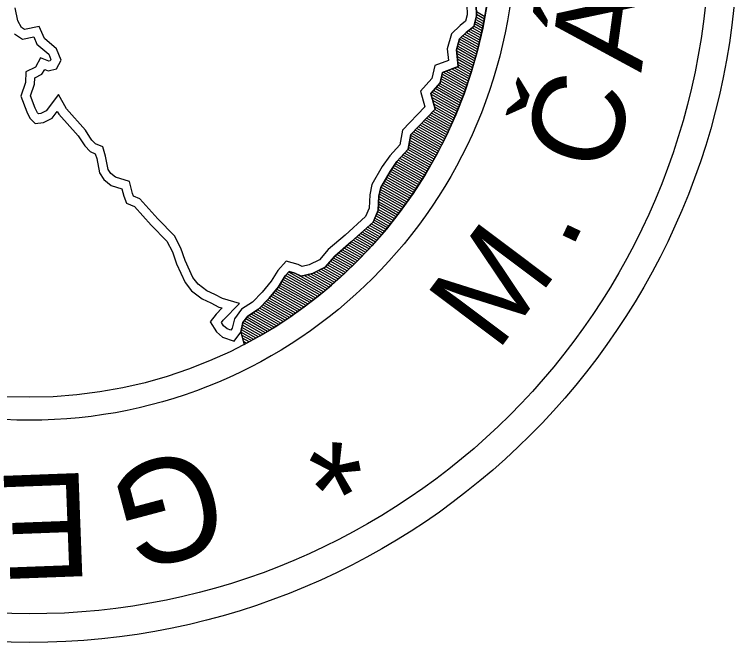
# Model space of a CAD drawing. Extents: x -821057 to -820632, y -1070881 to -1069829.
# Drawn here: x -820964.313 to -820960.375, y -1069882.387 to -1069878.964 of the extents above; entities that cross this region are included whole.
import ezdxf

# ---------------------------------------------------------------- set-up
doc = ezdxf.new("R2010")
doc.units = 0
doc.layers.add('Popisove_pole', color=7, linetype='Continuous')

msp = doc.modelspace()

# ---------------------------------------------------------------- linework, layer by layer
at = {"layer": 'Popisove_pole'}
for p, q in [((-820961.7512, -1069878.9763), (-820961.7975, -1069878.9501)), ((-820961.7536, -1069878.9893), (-820961.7969, -1069878.9648)), ((-820961.7611, -1069879.0281), (-820961.8049, -1069879.0034)), ((-820961.7585, -1069879.0152), (-820961.8016, -1069878.9909)), ((-820961.756, -1069879.0023), (-820961.7984, -1069878.9784)), ((-820961.772, -1069879.0794), (-820961.8318, -1069879.0456)), ((-820961.7692, -1069879.0666), (-820961.8211, -1069879.0373)), ((-820961.7664, -1069879.0538), (-820961.8114, -1069879.0284)), ((-820961.7637, -1069879.041), (-820961.8082, -1069879.0159)), ((-820961.7838, -1069879.1301), (-820961.8722, -1069879.0802)), ((-820961.7808, -1069879.1175), (-820961.8627, -1069879.0712)), ((-820961.7778, -1069879.1048), (-820961.8533, -1069879.0622)), ((-820961.7748, -1069879.0921), (-820961.8426, -1069879.0539)), ((-820961.7967, -1069879.1803), (-820961.8969, -1069879.1237)), ((-820961.7934, -1069879.1678), (-820961.8934, -1069879.1113)), ((-820961.7901, -1069879.1553), (-820961.8898, -1069879.099)), ((-820961.7869, -1069879.1427), (-820961.8816, -1069879.0892)), ((-820961.8069, -1069879.2176), (-820961.9056, -1069879.1618)), ((-820961.8034, -1069879.2052), (-820961.9041, -1069879.1483)), ((-820961.8, -1069879.1928), (-820961.9005, -1069879.136)), ((-820961.8104, -1069879.23), (-820961.9038, -1069879.1772)), ((-820961.814, -1069879.2423), (-820961.902, -1069879.1926)), ((-820961.8177, -1069879.2546), (-820961.9002, -1069879.208)), ((-820961.8214, -1069879.2668), (-820961.8984, -1069879.2234)), ((-820961.8252, -1069879.2791), (-820961.8965, -1069879.2387)), ((-820961.849, -1069879.3518), (-820961.9785, -1069879.2786)), ((-820961.8449, -1069879.3397), (-820961.9633, -1069879.2728)), ((-820961.8408, -1069879.3277), (-820961.9482, -1069879.267)), ((-820961.8368, -1069879.3156), (-820961.933, -1069879.2612)), ((-820961.8329, -1069879.3034), (-820961.9178, -1069879.2555)), ((-820961.829, -1069879.2913), (-820961.9026, -1069879.2497)), ((-820961.8617, -1069879.3877), (-820961.9895, -1069879.3154)), ((-820961.8574, -1069879.3757), (-820961.9865, -1069879.3027)), ((-820961.8532, -1069879.3638), (-820961.9835, -1069879.2901)), ((-820961.8794, -1069879.4351), (-820962.0142, -1069879.3589)), ((-820961.8748, -1069879.4233), (-820962.0059, -1069879.3493)), ((-820961.8704, -1069879.4115), (-820961.9975, -1069879.3396)), ((-820961.866, -1069879.3996), (-820961.9925, -1069879.3281)), ((-820961.8979, -1069879.482), (-820962.0445, -1069879.3992)), ((-820961.8932, -1069879.4704), (-820962.0394, -1069879.3878)), ((-820961.8885, -1069879.4586), (-820962.031, -1069879.3781)), ((-820961.8839, -1069879.4469), (-820962.0226, -1069879.3685)), ((-820961.9027, -1069879.4937), (-820962.0397, -1069879.4163)), ((-820961.9076, -1069879.5053), (-820962.0348, -1069879.4334)), ((-820961.9125, -1069879.5169), (-820962.0299, -1069879.4505)), ((-820961.9174, -1069879.5285), (-820962.0251, -1069879.4676)), ((-820961.9378, -1069879.5744), (-820962.0502, -1069879.5109)), ((-820961.9326, -1069879.563), (-820962.0413, -1069879.5015)), ((-820961.9275, -1069879.5515), (-820962.0324, -1069879.4922)), ((-820961.9224, -1069879.54), (-820962.0235, -1069879.4829)), ((-820961.9644, -1069879.6311), (-820962.0947, -1069879.5575)), ((-820961.959, -1069879.6198), (-820962.0858, -1069879.5482)), ((-820961.9536, -1069879.6085), (-820962.0769, -1069879.5388)), ((-820961.9483, -1069879.5972), (-820962.068, -1069879.5295)), ((-820961.943, -1069879.5858), (-820962.0591, -1069879.5202)), ((-820961.9867, -1069879.6759), (-820962.1303, -1069879.5948)), ((-820961.9811, -1069879.6648), (-820962.1214, -1069879.5855)), ((-820961.9755, -1069879.6536), (-820962.1125, -1069879.5761)), ((-820961.9699, -1069879.6424), (-820962.1036, -1069879.5668)), ((-820962.0099, -1069879.7203), (-820962.1569, -1069879.6372)), ((-820962.004, -1069879.7092), (-820962.1545, -1069879.6242)), ((-820961.9982, -1069879.6982), (-820962.1482, -1069879.6134)), ((-820961.9924, -1069879.6871), (-820962.1393, -1069879.6041)), ((-820962.0278, -1069879.7532), (-820962.1642, -1069879.6762)), ((-820962.0218, -1069879.7423), (-820962.1617, -1069879.6632)), ((-820962.0158, -1069879.7313), (-820962.1593, -1069879.6502)), ((-820962.0463, -1069879.7859), (-820962.1798, -1069879.7104)), ((-820962.0401, -1069879.775), (-820962.1712, -1069879.7009)), ((-820962.0339, -1069879.7641), (-820962.1666, -1069879.6892)), ((-820962.0716, -1069879.829), (-820962.2144, -1069879.7483)), ((-820962.0652, -1069879.8183), (-820962.2058, -1069879.7388)), ((-820962.0588, -1069879.8075), (-820962.1971, -1069879.7293)), ((-820962.0525, -1069879.7967), (-820962.1885, -1069879.7199)), ((-820962.0978, -1069879.8716), (-820962.2457, -1069879.788)), ((-820962.0912, -1069879.861), (-820962.2386, -1069879.7777)), ((-820962.0846, -1069879.8504), (-820962.2314, -1069879.7674)), ((-820962.0781, -1069879.8397), (-820962.223, -1069879.7578)), ((-820962.1249, -1069879.9137), (-820962.2735, -1069879.8298)), ((-820962.118, -1069879.9033), (-820962.2672, -1069879.819)), ((-820962.1112, -1069879.8927), (-820962.26, -1069879.8087)), ((-820962.1045, -1069879.8822), (-820962.2529, -1069879.7983)), ((-820962.1528, -1069879.9554), (-820962.2984, -1069879.8731)), ((-820962.1457, -1069879.945), (-820962.2921, -1069879.8623)), ((-820962.1387, -1069879.9346), (-820962.2859, -1069879.8515)), ((-820962.1318, -1069879.9242), (-820962.2797, -1069879.8406)), ((-820962.1743, -1069879.9863), (-820962.3171, -1069879.9056)), ((-820962.1671, -1069879.976), (-820962.3108, -1069879.8948)), ((-820962.1599, -1069879.9657), (-820962.3046, -1069879.884)), ((-820962.1964, -1069880.0169), (-820962.3257, -1069879.9439)), ((-820962.189, -1069880.0068), (-820962.3231, -1069879.931)), ((-820962.1816, -1069879.9965), (-820962.3205, -1069879.9181)), ((-820962.2189, -1069880.0473), (-820962.3295, -1069879.9848)), ((-820962.2113, -1069880.0372), (-820962.3287, -1069879.9709)), ((-820962.2038, -1069880.0271), (-820962.3279, -1069879.957)), ((-820962.2419, -1069880.0774), (-820962.332, -1069880.0264)), ((-820962.2342, -1069880.0674), (-820962.3312, -1069880.0125)), ((-820962.2265, -1069880.0573), (-820962.3303, -1069879.9986)), ((-820962.2654, -1069880.1071), (-820962.3451, -1069880.0621)), ((-820962.2575, -1069880.0972), (-820962.3403, -1069880.0504)), ((-820962.2497, -1069880.0873), (-820962.3356, -1069880.0387)), ((-820962.2975, -1069880.1464), (-820962.3698, -1069880.1056)), ((-820962.2894, -1069880.1366), (-820962.36, -1069880.0968)), ((-820962.2814, -1069880.1268), (-820962.3545, -1069880.0855)), ((-820962.2733, -1069880.117), (-820962.3498, -1069880.0738)), ((-820962.339, -1069880.1948), (-820962.4188, -1069880.1497)), ((-820962.3306, -1069880.1852), (-820962.409, -1069880.1408)), ((-820962.3222, -1069880.1755), (-820962.3992, -1069880.132)), ((-820962.3139, -1069880.1659), (-820962.3894, -1069880.1232)), ((-820962.3057, -1069880.1561), (-820962.3796, -1069880.1144)), ((-820962.3732, -1069880.2329), (-820962.458, -1069880.1849)), ((-820962.3645, -1069880.2234), (-820962.4482, -1069880.1761)), ((-820962.356, -1069880.2139), (-820962.4384, -1069880.1673)), ((-820962.3474, -1069880.2043), (-820962.4286, -1069880.1585)), ((-820962.4172, -1069880.2798), (-820962.5077, -1069880.2286)), ((-820962.4083, -1069880.2705), (-820962.4977, -1069880.22)), ((-820962.3994, -1069880.2611), (-820962.4876, -1069880.2113)), ((-820962.3906, -1069880.2517), (-820962.4776, -1069880.2026)), ((-820962.3819, -1069880.2423), (-820962.4678, -1069880.1938)), ((-820962.4536, -1069880.3167), (-820962.5479, -1069880.2633)), ((-820962.4444, -1069880.3075), (-820962.5379, -1069880.2547)), ((-820962.4353, -1069880.2983), (-820962.5278, -1069880.246)), ((-820962.4262, -1069880.289), (-820962.5178, -1069880.2373)), ((-820962.4909, -1069880.353), (-820962.5849, -1069880.2999)), ((-820962.4814, -1069880.344), (-820962.5765, -1069880.2903)), ((-820962.4721, -1069880.3349), (-820962.568, -1069880.2807)), ((-820962.4628, -1069880.3258), (-820962.558, -1069880.272)), ((-820962.5388, -1069880.3977), (-820962.6305, -1069880.3459)), ((-820962.5291, -1069880.3888), (-820962.6186, -1069880.3383)), ((-820962.5195, -1069880.3799), (-820962.6102, -1069880.3287)), ((-820962.5099, -1069880.371), (-820962.6018, -1069880.3191)), ((-820962.5003, -1069880.362), (-820962.5933, -1069880.3095)), ((-820962.6396, -1069880.4843), (-820962.8279, -1069880.3779)), ((-820962.6292, -1069880.4758), (-820962.8194, -1069880.3684)), ((-820962.6189, -1069880.4673), (-820962.7694, -1069880.3823)), ((-820962.5985, -1069880.4501), (-820962.7176, -1069880.3828)), ((-820962.5884, -1069880.4415), (-820962.6994, -1069880.3788)), ((-820962.5784, -1069880.4328), (-820962.6836, -1069880.3734)), ((-820962.5684, -1069880.4241), (-820962.6703, -1069880.3665)), ((-820962.5585, -1069880.4153), (-820962.657, -1069880.3596)), ((-820962.5486, -1069880.4065), (-820962.6438, -1069880.3528)), ((-820962.6818, -1069880.5179), (-820962.8565, -1069880.4192)), ((-820962.6711, -1069880.5096), (-820962.8499, -1069880.4086)), ((-820962.6606, -1069880.5012), (-820962.8433, -1069880.398)), ((-820962.6501, -1069880.4928), (-820962.8364, -1069880.3875)), ((-820962.6087, -1069880.4587), (-820962.7359, -1069880.3869)), ((-820962.725, -1069880.5509), (-820962.8849, -1069880.4606)), ((-820962.7141, -1069880.5427), (-820962.8768, -1069880.4508)), ((-820962.7033, -1069880.5345), (-820962.8697, -1069880.4404)), ((-820962.6925, -1069880.5262), (-820962.8631, -1069880.4298)), ((-820962.7694, -1069880.5833), (-820962.9171, -1069880.4998)), ((-820962.7582, -1069880.5753), (-820962.909, -1069880.49)), ((-820962.7471, -1069880.5672), (-820962.901, -1069880.4802)), ((-820962.736, -1069880.5591), (-820962.8929, -1069880.4704)), ((-820962.815, -1069880.615), (-820962.9518, -1069880.5377)), ((-820962.8035, -1069880.6071), (-820962.9428, -1069880.5283)), ((-820962.792, -1069880.5992), (-820962.9339, -1069880.519)), ((-820962.7807, -1069880.5913), (-820962.9252, -1069880.5096)), ((-820962.8736, -1069880.6536), (-820963.0006, -1069880.5819)), ((-820962.8617, -1069880.646), (-820962.9887, -1069880.5742)), ((-820962.8499, -1069880.6383), (-820962.9785, -1069880.5656)), ((-820962.8382, -1069880.6306), (-820962.9696, -1069880.5563)), ((-820962.8265, -1069880.6228), (-820962.9607, -1069880.547)), ((-820962.9219, -1069880.6838), (-820963.0459, -1069880.6137)), ((-820962.9097, -1069880.6763), (-820963.0364, -1069880.6047)), ((-820962.8976, -1069880.6688), (-820963.0245, -1069880.5971)), ((-820962.8855, -1069880.6612), (-820963.0125, -1069880.5895)), ((-820962.9715, -1069880.7132), (-820963.0717, -1069880.6566)), ((-820962.959, -1069880.7059), (-820963.0689, -1069880.6438)), ((-820962.9465, -1069880.6986), (-820963.0612, -1069880.6338)), ((-820962.9342, -1069880.6912), (-820963.0535, -1069880.6237)), ((-820963.0096, -1069880.7347), (-820963.08, -1069880.6949)), ((-820963.08, -1069880.6952), (-820963.0618, -1069880.7629)), ((-820963.08, -1069880.6952), (-820963.0618, -1069880.7629)), ((-820962.9968, -1069880.7276), (-820963.0772, -1069880.6821)), ((-820962.9841, -1069880.7204), (-820963.0744, -1069880.6694)), ((-820963.0225, -1069880.7418), (-820963.0755, -1069880.7118)), ((-820963.0354, -1069880.7488), (-820963.071, -1069880.7287)), ((-820963.0485, -1069880.7558), (-820963.0664, -1069880.7457)), ((-820963.0616, -1069880.7628), (-820963.0619, -1069880.7626))]:
    msp.add_line(p, q, dxfattribs=at)
for points in [[(-820961.8491, -1069878.9119), (-820961.8469, -1069878.9663), (-820961.856, -1069879.001), (-820961.8858, -1069879.0241), (-820961.9333, -1069879.0694), (-820961.9571, -1069879.1519), (-820961.9498, -1069879.2142), (-820962.0236, -1069879.2422), (-820962.0403, -1069879.3126), (-820962.1012, -1069879.3827), (-820962.0773, -1069879.4669), (-820962.1999, -1069879.5953), (-820962.2147, -1069879.6744), (-820962.2692, -1069879.7341), (-820962.3097, -1069879.7926), (-820962.3658, -1069879.8901), (-820962.3774, -1069879.9472), (-820962.3817, -1069880.0192), (-820962.4005, -1069880.066), (-820962.512, -1069880.1662), (-820962.6036, -1069880.2453), (-820962.6524, -1069880.3009), (-820962.7071, -1069880.3293), (-820962.7462, -1069880.338), (-820962.7678, -1069880.3275), (-820962.8332, -1069880.3084), (-820962.8779, -1069880.359), (-820962.915, -1069880.4185), (-820962.9639, -1069880.478), (-820963.0157, -1069880.5322), (-820963.0759, -1069880.5706), (-820963.1154, -1069880.6223), (-820963.1266, -1069880.6742), (-820963.1348, -1069880.6853), (-820963.154, -1069880.6783), (-820963.1742, -1069880.6609), (-820963.1862, -1069880.6426), (-820963.1765, -1069880.6301), (-820963.0874, -1069880.5392), (-820963.1804, -1069880.5121), (-820963.2211, -1069880.4907), (-820963.2655, -1069880.4705), (-820963.313, -1069880.4338), (-820963.3406, -1069880.3981), (-820963.3838, -1069880.3051), (-820963.4064, -1069880.2387), (-820963.4411, -1069880.1698), (-820963.5312, -1069880.0783), (-820963.6293, -1069879.9688), (-820963.6638, -1069879.9543), (-820963.6691, -1069879.9399), (-820963.6869, -1069879.8742), (-820963.7629, -1069879.8515), (-820963.7883, -1069879.8309), (-820963.8017, -1069879.8089), (-820963.8166, -1069879.7358), (-820963.8321, -1069879.6863), (-820963.8716, -1069879.6692), (-820963.8911, -1069879.6488), (-820963.9022, -1069879.632), (-820963.9254, -1069879.5946), (-820964.0303, -1069879.479), (-820964.0734, -1069879.4011), (-820964.1402, -1069879.4892), (-820964.1692, -1069879.5038), (-820964.1825, -1069879.5055), (-820964.1878, -1069879.5003), (-820964.2001, -1069879.4747), (-820964.2254, -1069879.4082), (-820964.2034, -1069879.3448), (-820964.2023, -1069879.3093), (-820964.1629, -1069879.2903), (-820964.1481, -1069879.264), (-820964.13, -1069879.2712), (-820964.0845, -1069879.2598), (-820964.0592, -1069879.2134), (-820964.0843, -1069879.1513), (-820964.1492, -1069879.0955), (-820964.178, -1069879.0298), (-820964.2582, -1069879.0463), (-820964.2751, -1069879.0352), (-820964.2938, -1069878.9993), (-820964.3083, -1069878.9283)], [(-820964.2461, -1069879.4944), (-820964.2291, -1069879.5298), (-820964.2003, -1069879.5581), (-820964.1544, -1069879.5524), (-820964.1073, -1069879.5286), (-820964.08, -1069879.4925), (-820964.0712, -1069879.5083), (-820963.9655, -1069879.6249), (-820963.9443, -1069879.659), (-820963.9303, -1069879.6801), (-820963.9008, -1069879.7111), (-820963.8729, -1069879.7231), (-820963.8651, -1069879.7483), (-820963.849, -1069879.8275), (-820963.8265, -1069879.8643), (-820963.7867, -1069879.8966), (-820963.7279, -1069879.9141), (-820963.7168, -1069879.9552), (-820963.7032, -1069879.992), (-820963.659, -1069880.0105), (-820963.5676, -1069880.1125), (-820963.4823, -1069880.1993), (-820963.4527, -1069880.2581), (-820963.4303, -1069880.3238), (-820963.3836, -1069880.4242), (-820963.3486, -1069880.4695), (-820963.2915, -1069880.5136), (-820963.2431, -1069880.5356), (-820963.1992, -1069880.5587), (-820963.1816, -1069880.5638), (-820963.2142, -1069880.5971), (-820963.2475, -1069880.6401), (-820963.2122, -1069880.6941), (-820963.1797, -1069880.7222), (-820963.1166, -1069880.745), (-820963.08, -1069880.6952), (-820963.0689, -1069880.6438), (-820963.0415, -1069880.608), (-820962.9838, -1069880.5711), (-820962.9265, -1069880.5112), (-820962.8743, -1069880.4477), (-820962.8377, -1069880.389), (-820962.8167, -1069880.3653), (-820962.7858, -1069880.3744), (-820962.7523, -1069880.3905), (-820962.6899, -1069880.3766), (-820962.621, -1069880.341), (-820962.5683, -1069880.2809), (-820962.4789, -1069880.2037), (-820962.3585, -1069880.0954), (-820962.3322, -1069880.0304), (-820962.3277, -1069879.9537), (-820962.3184, -1069879.908), (-820962.2674, -1069879.8193), (-820962.23, -1069879.7654), (-820962.1681, -1069879.6976), (-820962.1535, -1069879.619), (-820962.0214, -1069879.4807), (-820962.0457, -1069879.3951), (-820961.9945, -1069879.3362), (-820961.981, -1069879.2795), (-820961.8956, -1069879.247), (-820961.9063, -1069879.1561), (-820961.889, -1069879.0963), (-820961.8531, -1069879.0621), (-820961.8119, -1069879.0301), (-820961.7966, -1069878.9718), (-820961.7992, -1069878.9084)], [(-820961.7992, -1069878.9084), (-820961.7966, -1069878.9718), (-820961.8119, -1069879.0301), (-820961.8531, -1069879.0621), (-820961.889, -1069879.0963), (-820961.9063, -1069879.1561), (-820961.8956, -1069879.247), (-820961.981, -1069879.2795), (-820961.9945, -1069879.3362), (-820962.0457, -1069879.3951), (-820962.0214, -1069879.4807), (-820962.1535, -1069879.619), (-820962.1681, -1069879.6976), (-820962.23, -1069879.7654), (-820962.2674, -1069879.8193), (-820962.3184, -1069879.908), (-820962.3277, -1069879.9537), (-820962.3322, -1069880.0304), (-820962.3585, -1069880.0954), (-820962.4789, -1069880.2037), (-820962.5683, -1069880.2809), (-820962.621, -1069880.341), (-820962.6899, -1069880.3766), (-820962.7523, -1069880.3905), (-820962.7858, -1069880.3744), (-820962.8167, -1069880.3653), (-820962.8377, -1069880.389), (-820962.8743, -1069880.4477), (-820962.9265, -1069880.5112), (-820962.9838, -1069880.5711), (-820963.0415, -1069880.608), (-820963.0689, -1069880.6438), (-820963.08, -1069880.6952)], [(-820964.3134, -1069879.0699), (-820964.2683, -1069879.0994), (-820964.2075, -1069879.0869), (-820964.1904, -1069879.126), (-820964.1261, -1069879.1813), (-820964.1144, -1069879.2102), (-820964.1179, -1069879.2166), (-820964.1265, -1069879.2188), (-820964.1703, -1069879.2013), (-820964.1988, -1069879.2521), (-820964.2513, -1069879.2774), (-820964.2531, -1069879.3356), (-820964.2786, -1069879.4089), (-820964.2461, -1069879.4944)]]:
    msp.add_lwpolyline(points, dxfattribs=at)
for radius in [3.8563, 3.7, 3.7, 2.6447, 2.6447, 2.5197]:
    msp.add_circle((-820964.2313, -1069878.531), radius, dxfattribs=at)
msp.add_arc((-820964.2313, -1069878.531), 2.5197, 297.6537, 75.4607, dxfattribs=at)

# ---------------------------------------------------------------- texts
for s, height, rotation, p in [('Á', 0.5, 82.1555, (-820960.8994, -1069879.2837)), ('Č', 0.5, 72.1985, (-820961.0797, -1069879.8485)), ('M', 0.5, 53.0591, (-820961.6859, -1069880.809)), ('.', 0.5, 64.5427, (-820961.2833, -1069880.2566)), ('*', 0.5625, 208.5393, (-820962.6344, -1069881.0095)), ('G', 0.5625, 194.9093, (-820963.2634, -1069881.3161)), ('E', 0.5625, 182.1445, (-820963.9027, -1069881.4611))]:
    msp.add_text(s, height=height, rotation=rotation, dxfattribs=at).set_placement(p)

doc.saveas('drawing.dxf')
